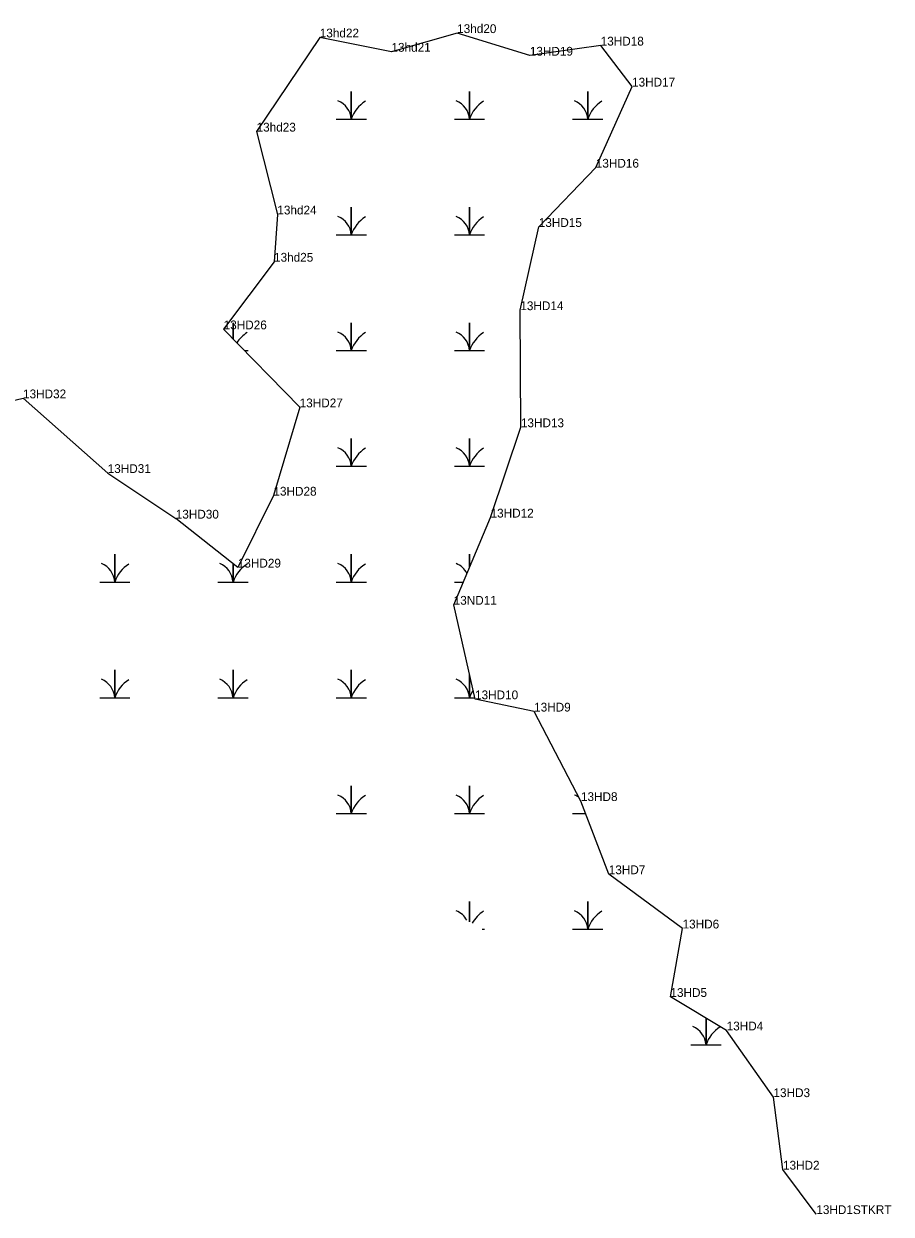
# Model space of a CAD drawing. Extents: x 2072529 to 2268796, y 436423 to 470397.
# Drawn here: x 2250761 to 2251255, y 444343 to 445020 of the extents above; entities that cross this region are included whole.
import ezdxf

# ---------------------------------------------------------------- set-up
doc = ezdxf.new("R2010")
doc.units = 0
for name, color, linetype in [('Exist Environmental Wetland Boundary', 7, 'Continuous'), ('Exist Environmental Wetland Boundary Cogo Comment', 7, 'Continuous'), ('Exist Environmental Wetland Boundary Cogo Point CELL', 7, 'Continuous'), ('Exist Hydro Swamp or Marsh', 7, 'Continuous')]:
    doc.layers.add(name, color=color, linetype=linetype)

msp = doc.modelspace()

# ---------------------------------------------------------------- linework, layer by layer
at = {"layer": 'Exist Environmental Wetland Boundary'}
for points in [[(2251212.23, 444343.52), (2251193.27, 444368.8), (2251187.87, 444410.03), (2251161.22, 444447.95), (2251129.26, 444466.99), (2251136.16, 444505.93), (2251094.18, 444536.79), (2251078.35, 444578.38), (2251051.73, 444629.28), (2251018.11, 444636.26), (2251005.97, 444690.02), (2251026.96, 444739.61), (2251044.21, 444790.96), (2251043.88, 444857.53), (2251054.36, 444904.84), (2251086.81, 444938.56), (2251107.42, 444984.69), (2251089.58, 445007.98), (2251049.29, 445002.24), (2251007.96, 445015.09), (2250970.61, 445004.47), (2250929.81, 445012.61), (2250893.89, 444959.07), (2250905.69, 444911.95), (2250903.81, 444885.08), (2250875.15, 444846.63), (2250918.38, 444802.27), (2250903.46, 444752.05), (2250883.19, 444711.16), (2250847.9, 444738.99)], [(2250569.67, 444960.92), (2250585.93, 444930.87), (2250595.62, 444918.67), (2250612.55, 444915.97), (2250626.97, 444915.57), (2250651.71, 444924.32), (2250673.66, 444910.05), (2250693.85, 444893.89), (2250683.12, 444874.09), (2250674.94, 444842.31), (2250679.43, 444809.37), (2250708.15, 444815.88), (2250724.47, 444827.73), (2250736.14, 444844.74), (2250737.08, 444838.53), (2250725.14, 444798.96), (2250761.04, 444807.39), (2250809.19, 444764.92), (2250847.9, 444738.99)]]:
    msp.add_lwpolyline(points, dxfattribs=at)
at = {"layer": 'Exist Environmental Wetland Boundary Cogo Point CELL'}
for p, q in [((2250929.81, 445012.61), (2250929.81, 445012.61)), ((2251007.96, 445015.09), (2251007.96, 445015.09)), ((2250970.61, 445004.47), (2250970.61, 445004.47)), ((2251049.29, 445002.24), (2251049.29, 445002.24)), ((2251089.58, 445007.98), (2251089.58, 445007.98)), ((2251107.42, 444984.69), (2251107.42, 444984.69)), ((2250893.89, 444959.07), (2250893.89, 444959.07)), ((2251086.81, 444938.56), (2251086.81, 444938.56)), ((2250905.69, 444911.95), (2250905.69, 444911.95)), ((2251054.36, 444904.84), (2251054.36, 444904.84)), ((2250903.81, 444885.08), (2250903.81, 444885.08)), ((2251043.88, 444857.53), (2251043.88, 444857.53)), ((2250875.15, 444846.63), (2250875.15, 444846.63)), ((2250918.38, 444802.27), (2250918.38, 444802.27)), ((2251044.21, 444790.96), (2251044.21, 444790.96)), ((2250809.19, 444764.92), (2250809.19, 444764.92)), ((2250903.46, 444752.05), (2250903.46, 444752.05)), ((2250847.9, 444738.99), (2250847.9, 444738.99)), ((2251026.96, 444739.61), (2251026.96, 444739.61)), ((2250883.19, 444711.16), (2250883.19, 444711.16)), ((2251005.97, 444690.02), (2251005.97, 444690.02)), ((2251018.11, 444636.26), (2251018.11, 444636.26)), ((2251051.73, 444629.28), (2251051.73, 444629.28)), ((2251078.35, 444578.38), (2251078.35, 444578.38)), ((2251094.18, 444536.79), (2251094.18, 444536.79)), ((2251136.16, 444505.93), (2251136.16, 444505.93)), ((2251129.26, 444466.99), (2251129.26, 444466.99)), ((2251161.22, 444447.95), (2251161.22, 444447.95)), ((2251187.87, 444410.03), (2251187.87, 444410.03)), ((2251193.27, 444368.8), (2251193.27, 444368.8)), ((2251212.23, 444343.52), (2251212.23, 444343.52))]:
    msp.add_line(p, q, dxfattribs=at)
at = {"layer": 'Exist Hydro Swamp or Marsh'}
for points in [[(2250939.14, 444966.14), (2250947.74, 444966.14), (2250947.74, 444981.92), (2250947.74, 444966.14), (2250956.34, 444966.14)], [(2251006.39, 444966.14), (2251014.99, 444966.14), (2251014.99, 444981.92), (2251014.99, 444966.14), (2251023.59, 444966.14)], [(2251073.64, 444966.14), (2251082.24, 444966.14), (2251082.24, 444981.92), (2251082.24, 444966.14), (2251090.84, 444966.14)], [(2250939.14, 444900.34), (2250947.74, 444900.34), (2250947.74, 444916.12), (2250947.74, 444900.34), (2250956.34, 444900.34)], [(2251006.39, 444900.34), (2251014.99, 444900.34), (2251014.99, 444916.12), (2251014.99, 444900.34), (2251023.59, 444900.34)], [(2250880.49, 444841.16), (2250880.49, 444850.32), (2250880.49, 444841.16)], [(2250939.14, 444834.54), (2250947.74, 444834.54), (2250947.74, 444850.32), (2250947.74, 444834.54), (2250956.34, 444834.54)], [(2251006.39, 444834.54), (2251014.99, 444834.54), (2251014.99, 444850.32), (2251014.99, 444834.54), (2251023.59, 444834.54)], [(2250886.94, 444834.54), (2250889.09, 444834.54)], [(2250939.14, 444768.74), (2250947.74, 444768.74), (2250947.74, 444784.52), (2250947.74, 444768.74), (2250956.34, 444768.74)], [(2251006.39, 444768.74), (2251014.99, 444768.74), (2251014.99, 444784.52), (2251014.99, 444768.74), (2251023.59, 444768.74)], [(2250804.64, 444768.74), (2250804.86, 444768.74)], [(2250804.64, 444702.94), (2250813.24, 444702.94), (2250813.24, 444718.72), (2250813.24, 444702.94), (2250821.84, 444702.94)], [(2250939.14, 444702.94), (2250947.74, 444702.94), (2250947.74, 444718.72), (2250947.74, 444702.94), (2250956.34, 444702.94)], [(2251014.99, 444711.33), (2251014.99, 444718.72), (2251014.99, 444711.33)], [(2250871.89, 444702.94), (2250880.49, 444702.94), (2250880.49, 444713.29)], [(2250880.49, 444713.29), (2250880.49, 444702.94), (2250889.09, 444702.94)], [(2251006.39, 444702.94), (2251011.44, 444702.94)], [(2250804.64, 444637.14), (2250813.24, 444637.14), (2250813.24, 444652.92), (2250813.24, 444637.14), (2250821.84, 444637.14)], [(2250871.89, 444637.14), (2250880.49, 444637.14), (2250880.49, 444652.92), (2250880.49, 444637.14), (2250889.09, 444637.14)], [(2250939.14, 444637.14), (2250947.74, 444637.14), (2250947.74, 444652.92), (2250947.74, 444637.14), (2250956.34, 444637.14)], [(2251006.39, 444637.14), (2251014.99, 444637.14), (2251014.99, 444650.09)], [(2251014.99, 444650.09), (2251014.99, 444637.14), (2251017.91, 444637.14)], [(2250939.14, 444571.34), (2250947.74, 444571.34), (2250947.74, 444587.12), (2250947.74, 444571.34), (2250956.34, 444571.34)], [(2251006.39, 444571.34), (2251014.99, 444571.34), (2251014.99, 444587.12), (2251014.99, 444571.34), (2251023.59, 444571.34)], [(2251073.64, 444571.34), (2251081.03, 444571.34)], [(2251014.99, 444509.72), (2251014.99, 444521.32), (2251014.99, 444509.72)], [(2251073.64, 444505.54), (2251082.24, 444505.54), (2251082.24, 444521.32), (2251082.24, 444505.54), (2251090.84, 444505.54)], [(2251022.21, 444505.54), (2251023.59, 444505.54)], [(2251140.89, 444439.74), (2251149.49, 444439.74), (2251149.49, 444454.94)], [(2251149.49, 444454.94), (2251149.49, 444439.74), (2251158.09, 444439.74)]]:
    msp.add_lwpolyline(points, dxfattribs=at)
for centre, radius, start, end in [((2250935.47, 444965.25), 12.3, 4.14034, 67.53497), ((2250965.98, 444960.08), 19.22, 122.12745, 161.62219), ((2251002.72, 444965.25), 12.3, 4.14034, 67.53497), ((2251033.23, 444960.08), 19.22, 122.12745, 161.62219), ((2251069.97, 444965.25), 12.3, 4.14034, 67.53497), ((2251100.48, 444960.08), 19.22, 122.12745, 161.62219), ((2250935.47, 444899.45), 12.3, 4.14034, 67.53497), ((2250965.98, 444894.28), 19.22, 122.12745, 161.62219), ((2251002.72, 444899.45), 12.3, 4.14034, 67.53497), ((2251033.23, 444894.28), 19.22, 122.12745, 161.62219), ((2250898.73, 444828.48), 19.22, 122.12745, 146.92978), ((2250935.47, 444833.65), 12.3, 4.14034, 67.53497), ((2250965.98, 444828.48), 19.22, 122.12745, 161.62219), ((2251002.72, 444833.65), 12.3, 4.14034, 67.53497), ((2251033.23, 444828.48), 19.22, 122.12745, 161.62219), ((2250935.47, 444767.85), 12.3, 4.14034, 67.53497), ((2250965.98, 444762.68), 19.22, 122.12745, 161.62219), ((2251002.72, 444767.85), 12.3, 4.14034, 67.53497), ((2251033.23, 444762.68), 19.22, 122.12745, 161.62219), ((2250800.97, 444702.05), 12.3, 4.14034, 67.53497), ((2250831.48, 444696.88), 19.22, 122.12745, 161.62219), ((2250868.22, 444702.05), 12.3, 4.14034, 67.53497), ((2250898.73, 444696.88), 19.22, 122.12745, 161.62219), ((2250935.47, 444702.05), 12.3, 4.14034, 67.53497), ((2250965.98, 444696.88), 19.22, 122.12745, 161.62219), ((2251002.72, 444702.05), 12.3, 28.40862, 67.53497), ((2250800.97, 444636.25), 12.3, 4.14034, 67.53497), ((2250831.48, 444631.08), 19.22, 122.12745, 161.62219), ((2250868.22, 444636.25), 12.3, 4.14034, 67.53497), ((2250898.73, 444631.08), 19.22, 122.12745, 161.62219), ((2250935.47, 444636.25), 12.3, 4.14034, 67.53497), ((2250965.98, 444631.08), 19.22, 122.12745, 161.62219), ((2251002.72, 444636.25), 12.3, 4.14034, 67.53497), ((2251033.23, 444631.08), 19.22, 147.78312, 161.62219), ((2250935.47, 444570.45), 12.3, 4.14034, 67.53497), ((2250965.98, 444565.28), 19.22, 122.12745, 161.62219), ((2251002.72, 444570.45), 12.3, 4.14034, 67.53497), ((2251033.23, 444565.28), 19.22, 122.12745, 161.62219), ((2251069.97, 444570.45), 12.3, 53.10498, 67.53497), ((2251002.72, 444504.65), 12.3, 28.89817, 67.53497), ((2251033.23, 444499.48), 19.22, 122.12745, 150.74827), ((2251069.97, 444504.65), 12.3, 4.14034, 67.53497), ((2251100.48, 444499.48), 19.22, 122.12745, 161.62219), ((2251137.22, 444438.85), 12.3, 4.14034, 67.53497), ((2251167.73, 444433.68), 19.22, 122.12745, 161.62219)]:
    msp.add_arc(centre, radius, start, end, dxfattribs=at)

# ---------------------------------------------------------------- texts
at = {"layer": 'Exist Environmental Wetland Boundary Cogo Comment'}
for s, p in [('13hd22', (2250929.81, 445012.61)), ('13hd20', (2251007.96, 445015.09)), ('13hd21', (2250970.61, 445004.47)), ('13HD18', (2251089.58, 445007.98)), ('13HD19', (2251049.29, 445002.24)), ('13HD17', (2251107.42, 444984.69)), ('13hd23', (2250893.89, 444959.07)), ('13HD16', (2251086.81, 444938.56)), ('13hd24', (2250905.69, 444911.95)), ('13HD15', (2251054.36, 444904.84)), ('13hd25', (2250903.81, 444885.08)), ('13HD14', (2251043.88, 444857.53)), ('13HD26', (2250875.15, 444846.63)), ('13HD32', (2250761.04, 444807.39)), ('13HD27', (2250918.38, 444802.27)), ('13HD13', (2251044.21, 444790.96)), ('13HD31', (2250809.19, 444764.92)), ('13HD28', (2250903.46, 444752.05)), ('13HD30', (2250847.9, 444738.99)), ('13HD12', (2251026.96, 444739.61)), ('13HD29', (2250883.19, 444711.16)), ('13ND11', (2251005.97, 444690.02)), ('13HD10', (2251018.11, 444636.26)), ('13HD9', (2251051.73, 444629.28)), ('13HD8', (2251078.35, 444578.38)), ('13HD7', (2251094.18, 444536.79)), ('13HD6', (2251136.16, 444505.93)), ('13HD5', (2251129.26, 444466.99)), ('13HD4', (2251161.22, 444447.95)), ('13HD3', (2251187.87, 444410.03)), ('13HD2', (2251193.27, 444368.8)), ('13HD1STKRT', (2251212.23, 444343.52))]:
    msp.add_text(s, height=5, dxfattribs=at).set_placement(p)

doc.saveas('drawing.dxf')
